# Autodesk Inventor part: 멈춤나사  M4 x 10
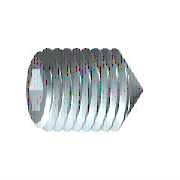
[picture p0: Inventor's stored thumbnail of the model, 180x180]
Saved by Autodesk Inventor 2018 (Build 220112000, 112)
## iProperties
Created: 2012-02
Part Number: 멈춤나사  M4 x 10
Material: 강철, 연강
Description: 6각 소켓 머리 없는 멈춤 나사
Document SubType Name: Modeling
Standard: KS B 1028
Designer: mduedu
Standards Organization: KS
Language: ko-KR
Size Designation: 원추점 M4x10
Categories: <MemberInstance><Categories><Category DisplayName="조임쇠" InternalName="e4da775c-781d-43d5-af7c-5136215cf5a6" Mnemonic="FSTN"><Category DisplayName="볼트" InternalN
Density: 7.86 g/cm^3
Mass: 0.792069 g
Surface Area: 1.48192 cm^2
Volume: 0.100772 cm^3
Appearance: 강철
Author: mduedu
IsCustomPart: 1
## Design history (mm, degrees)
sketch "스케치1"
  geometry: L1 (0, 0)-(6.833, 0); L2 (10, 1.155)-(10, 2); L3 (10, 2)-(0, 2); L4 (10, 1.155)-(7.5, 1.155); L5 (7.5, 1.155)-(6.833, 0); L6 (0, -0.4)-(0, 2.4) reference; L7 (0, 2)-(0, 0)
  constraints: 13 end point, 3 parallel, 1 collinear, 1 perpendicular, 1 point on line
  dimensions: "d0" = 2.5 distance of L2.start L4.end (= INTI); "d1" = 60 deg angle of L5 L1; "d2" = 4 diameter of L3 L1 (= NND); "d3" = 2.3094 diameter of L4 L1 (= 1.1547 x SW); "d5" = 10 distance from line of L2 L3.end (= NLG)
revolve "본체" sketch "스케치1" stored, may be unused: angle "d6" = 90 deg
sketch "스케치2"
  geometry: L1 (-0.577, 1)-(0.577, 1); L2 (0.577, 1)-(1.155, 0); L3 (1.155, 0)-(0.577, -1); L4 (0.577, -1)-(-0.577, -1); L5 (-0.577, -1)-(-1.155, 0); L6 (-1.155, 0)-(-0.577, 1); 3 further points
  constraints: 12 end point, 1 coincident, 1 horizontal, 13 other
extrude "슬롯" join sketch "스케치2" taper "d7" = 0 deg; stored distance "d21" = 10
workaxis "Work Axis1"
workplane "Work Plane1"
sketch "스케치4"
  geometry: L1 (-5, 0.2)-(-3.2, 2) reference; L2 (-5, -0.2)-(-3.2, -2) reference; L3 (-3.2, 2)-(-5.2, 0); L4 (-3.2, -2)-(-5.2, 0); 2 further points
  constraints: 4 end point, 2 collinear, 1 coincident
body "Solid1"
feature "스레드" dims "d12" = 10 (= NLG), "d13" = 0
chamfer "모따기1" distance "d8" = 1.8 (computed from NND, SPD, FAWI); stored, may be unused: angle "d9" = 45 deg (= FAWI), second distance "d34" = 1.8 (computed from NND, SPD, FAWI)
chamfer "모따기2" distance "d10" = 0.42941 (= -0.5 x GD1 + 0.5 x NND); stored, may be unused: angle "d11" = 45 deg (= FAWI), second distance "d35" = 0.42941 (= -0.5 x GD1 + 0.5 x NND)
other parameters: "NND" = 4 [user parameter; used in 5 equation terms], "NLG" = 10 [user parameter; used in 2 equation terms], "INTI" = 2.5 [user parameter; used in 1 equation term], "FAWI" = 45 deg [user parameter; used in 4 equation terms], "SW" = 2 [user parameter; used in 2 equation terms], "GD1" = 3.14117 (= THREADDIA - 1.2269 x PTC) [user parameter; used in 2 equation terms], "d4" = 0, "FAWI1" = 45 deg [user parameter], "SPD" = 0.4 [user parameter; used in 2 equation terms], "d36" = 0, "d37" = 0, "GUL" = 0.42941 (= 0.61345 x PTC) [user parameter], "TPU" = 14.28571 (computed from PTC) [user parameter], "TOA" = 30 deg [user parameter], "THREADDIA" = 4 [user parameter; used in 1 equation term], "PTC" = 0.7 [user parameter; used in 4 equation terms], "GAL" = 0.42941 (= 0.61345 x PTC) [user parameter], "E0" = 2.31 (= 1.155 x SW) [user parameter]
